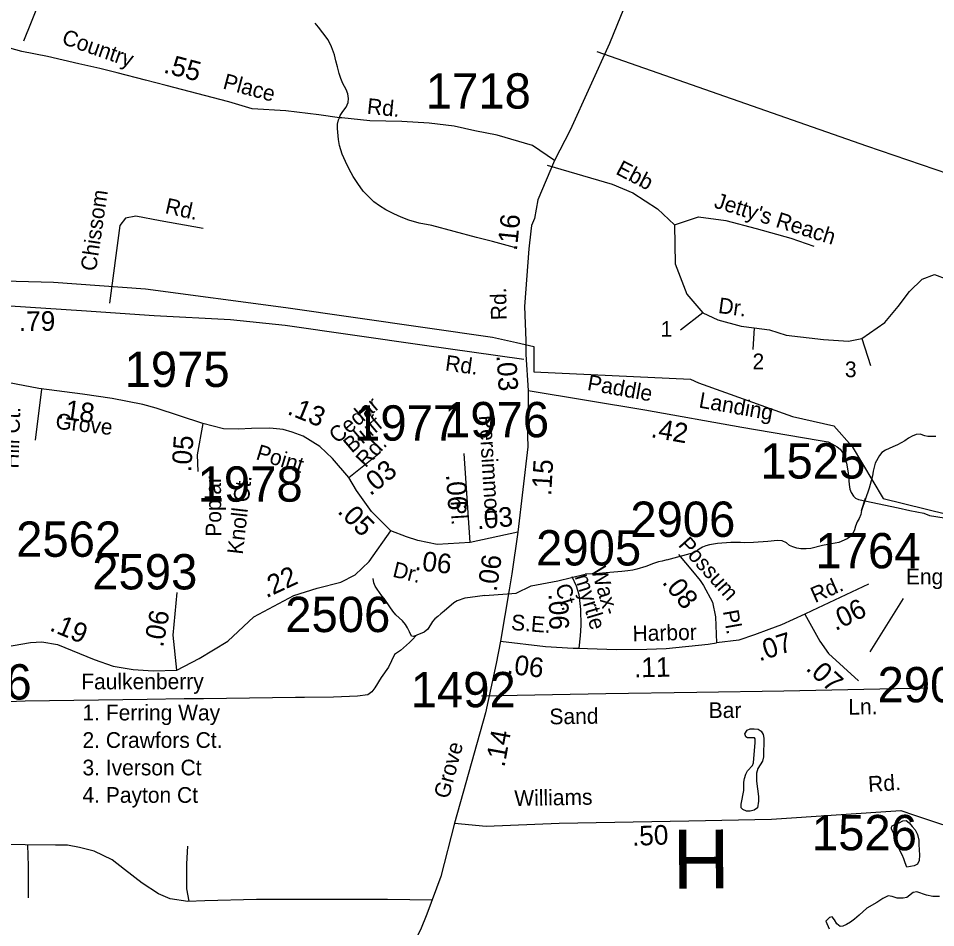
# Model space of a CAD drawing. Extents: x 1945482 to 2853149, y 66427 to 1015778.
# Drawn here: x 2335176 to 2339010, y 129311 to 133113 of the extents above; entities that cross this region are included whole.
import ezdxf

# ---------------------------------------------------------------- set-up
doc = ezdxf.new("R2010")
doc.units = 0
for name, color, linetype in [('Old_Level_10', 7, 'Continuous'), ('Old_Level_11', 7, 'Continuous'), ('Old_Level_17', 7, 'Continuous'), ('Old_Level_22', 7, 'Continuous'), ('Old_Level_32', 7, 'Continuous'), ('Old_Level_35', 7, 'Continuous'), ('Old_Level_50', 7, 'Continuous'), ('Old_Level_59', 7, 'Continuous'), ('Old_Level_60', 7, 'Continuous'), ('Old_Level_8', 7, 'Continuous')]:
    doc.layers.add(name, color=color, linetype=linetype)

msp = doc.modelspace()

# ---------------------------------------------------------------- linework, layer by layer
at = {"layer": 'Old_Level_11'}
msp.add_lwpolyline([(2338874.8, 130686.6), (2338735.5, 130464.3)], dxfattribs=at)
at = {"layer": 'Old_Level_32'}
msp.add_line((2337296.9, 131707.1), (2337306.5, 131557.2), dxfattribs=at)
for points in [[(2338269.9, 134469.8), (2338210.3, 134298.6), (2338141.2, 134156.7), (2338029, 133917.9), (2337971.8, 133774.7), (2337926.8, 133681.5), (2337881.7, 133575.2), (2337736.8, 133227.3), (2337646.7, 133008.3), (2337482.6, 132645.4), (2337417.3, 132518.6)], [(2337417.3, 132518.6), (2337325.2, 132580.9), (2337177.2, 132623.9), (2337084.2, 132643), (2336998.3, 132662.1), (2336893.3, 132674.1), (2336778.8, 132681.2), (2336644.7, 132683.7), (2336527.9, 132696.3), (2336518, 132697.5), (2336431.9, 132708.8), (2336294.3, 132725.5), (2336153.4, 132735.1), (2336056.6, 132763.2), (2335794.6, 132831.9), (2335707.2, 132853.7), (2335588.6, 132885), (2335516.9, 132903.7), (2335429.5, 132922.4), (2335298.5, 132953.6), (2335190.1, 132974.4), (2335073.8, 133006.7)], [(2337417.3, 132518.6), (2337347.8, 132353.3), (2337333.5, 132275.3), (2337320.8, 132246.7), (2337317.6, 132222.8), (2337310.1, 132148.8), (2337292.2, 131907.7), (2337296.9, 131766), (2337296.9, 131707.1)], [(2337288.4, 131685.7), (2336864, 131746.5), (2336290.8, 131828.4), (2336063.3, 131852.7), (2335744.1, 131869.4), (2335440, 131890.5), (2335141.6, 131909.2), (2335069.6, 131912.3), (2335007.5, 131913.8), (2334951.4, 131913.2), (2334907.5, 131912.8), (2334869.4, 131912.3), (2334835.4, 131909.9), (2334799.3, 131907.9), (2334666, 131893.1), (2334495.9, 131870.6), (2334240.3, 131832.4), (2333933.4, 131803.5), (2333526.6, 131748.4), (2333222.2, 131711.6), (2333101.9, 131703.9)], [(2335947.6, 131419), (2335752.8, 131483.3), (2335697.1, 131498.3), (2335567.8, 131523.9), (2335443.7, 131541.4), (2335261.5, 131564.6), (2335070.7, 131601.4)], [(2337306.5, 131557.2), (2337306.5, 131458.8), (2337303.3, 131414.3), (2337305.1, 131321.8), (2337263.4, 130963.7)], [(2337306.5, 131557.2), (2337795.2, 131475.6), (2338199.7, 131403.6), (2338518.6, 131348.9), (2338560.6, 131341.4), (2338579.7, 131332.3), (2338598.1, 131321.8), (2338611, 131311.8), (2338621.1, 131297.1), (2338629.3, 131280.1), (2338637.6, 131253.5), (2338644.5, 131212.4), (2338648.3, 131164.3), (2338651.4, 131144.1), (2338656.6, 131129.5), (2338667, 131114.5), (2338675.2, 131106.6), (2338687.3, 131100.5), (2338853.2, 131066.2), (2338902.9, 131054.8), (2338960.3, 131043.3), (2338985.1, 131033.7), (2339334.8, 130978.3)], [(2335947.6, 131419), (2335924, 131287.3), (2335926.3, 131218.6)], [(2336557, 131192.6), (2336489.5, 131271.7), (2336436.3, 131322.9), (2336366.7, 131365.8), (2336320.7, 131382.9), (2336283.2, 131393.6), (2336228, 131399.8), (2336150.7, 131397.6), (2336095.9, 131394.7), (2336033.2, 131396.5), (2335947.6, 131419)], [(2336557, 131192.6), (2336689.9, 131298.3)], [(2337065.3, 130920.5), (2337039.6, 131293.2)], [(2336733.6, 130969.8), (2336652.3, 131051.2), (2336590.2, 131137.9), (2336557, 131192.6)], [(2335838.6, 130387.5), (2335932.2, 130435.5), (2336051.4, 130509.1), (2336160.8, 130610.6), (2336327.8, 130700.1), (2336425.2, 130729.9), (2336524.6, 130755.8), (2336584.3, 130785.6), (2336642.6, 130842.3), (2336733.6, 130969.8)], [(2337065.3, 130920.5), (2336926.1, 130912.9), (2336846, 130930.1), (2336798.9, 130945.1), (2336733.6, 130969.8)], [(2337263.4, 130963.7), (2337065.3, 130920.5)], [(2337263.4, 130963.7), (2337239.5, 130790.6), (2337227.3, 130723.5), (2337191.7, 130508.3)], [(2337935.3, 130870.4), (2337994.5, 130801.2), (2338026.1, 130762), (2338040.3, 130741.2), (2338077.8, 130671.4), (2338090.3, 130609.7), (2338094.5, 130501.3)], [(2337489.6, 130778.5), (2337507.8, 130739.9), (2337518.8, 130703.4), (2337525.5, 130640.8), (2337527.2, 130574), (2337524.6, 130531.5), (2337518.3, 130479.1)], [(2338729.4, 130746.2), (2338492.3, 130634.9), (2338464, 130621.8)], [(2335838.6, 130387.5), (2335822.8, 130533), (2335840.3, 130711.6)], [(2338464, 130621.8), (2338365.4, 130577.5), (2338313, 130557.9), (2338253.6, 130534.4), (2338187.9, 130513.1), (2338094.5, 130501.3)], [(2338464, 130621.8), (2338525.8, 130508.6), (2338562.4, 130457.4), (2338688.4, 130342.2)], [(2338464, 130621.8), (2338525.8, 130508.6), (2338562.4, 130457.4), (2338688.4, 130342.2)], [(2334813.2, 130409.2), (2334949.8, 130429.7), (2335089.2, 130479.3), (2335226.4, 130503.2), (2335274.1, 130505.2), (2335339.7, 130495.2), (2335492.8, 130431.6), (2335572.3, 130403.7), (2335655.8, 130389.8), (2335739.3, 130383.8), (2335838.6, 130387.5)], [(2337191.7, 130508.3), (2337173.5, 130414.5), (2337129.2, 130208.7), (2336999.8, 129747.6)], [(2337191.7, 130508.3), (2337379.7, 130485.9), (2337495.3, 130479.6), (2337518.3, 130479.1)], [(2337518.3, 130479.1), (2337555.1, 130478.3), (2337675.8, 130473.2), (2337802.9, 130475.7), (2337884.5, 130478.5), (2338059.9, 130496.4), (2338094.5, 130501.3)], [(2336999.8, 129747.6), (2337131.7, 129735.1), (2337436.8, 129748), (2337978.5, 129757.9), (2338324.1, 129763.6), (2338864.3, 129799.9), (2338921.3, 129780.9), (2339039.3, 129741.9), (2339267.2, 129757.4)], [(2336999.8, 129747.6), (2336941.9, 129524.2), (2336883.7, 129367.1), (2336856.6, 129301.2), (2336804.6, 129200.6), (2336456.6, 128397.8), (2336312.3, 128078.6), (2336166, 127764.9), (2335959.9, 127274.1), (2335938.2, 127216)]]:
    msp.add_lwpolyline(points, dxfattribs=at)
at = {"layer": 'Old_Level_35'}
for points in [[(2335363.2, 133430.3), (2335197.3, 133017.7)], [(2336518, 132697.5), (2336521.7, 132706.3), (2336532.1, 132723.1), (2336546.8, 132742), (2336551.1, 132750.7), (2336554.3, 132761), (2336555.6, 132777.2), (2336553.5, 132797.1), (2336546.9, 132815.2), (2336532.7, 132840.9), (2336524.7, 132861), (2336517.3, 132882.3), (2336510, 132910.6), (2336503.8, 132934.6), (2336497.8, 132960.7), (2336485.7, 132994), (2336471.1, 133022.3), (2336448.6, 133052.3), (2336430.6, 133076.2), (2336416.2, 133092)], [(2337593.5, 132974.1), (2338721.8, 132579.2), (2339292, 132385.1)], [(2337250.1, 132154.1), (2337157.9, 132179.3), (2337091.5, 132196.7), (2336905.1, 132246.8), (2336850.9, 132256.2), (2336808.7, 132269.6), (2336776.7, 132281.4), (2336745.9, 132296), (2336712.5, 132312.7), (2336686.2, 132328.4), (2336661.9, 132346.2), (2336638.4, 132368.9), (2336617.5, 132389.7), (2336595.3, 132421.6), (2336576.3, 132452.1), (2336559.4, 132482.6), (2336543.7, 132514.1), (2336530, 132545.1), (2336518.7, 132581.1), (2336514.1, 132606.5), (2336510.9, 132636.6), (2336510, 132652), (2336510.6, 132670.7), (2336514.5, 132688.9), (2336518, 132697.5)], [(2337385.9, 132499.6), (2337658.7, 132419.8), (2337744, 132382.7), (2337847.9, 132315.9), (2337918.4, 132249.1), (2337922.1, 132085.7), (2337970.4, 131959.5), (2338037.2, 131881.5), (2338100.2, 131851.8), (2338196.7, 131825.8), (2338252.3, 131818.4), (2338315.4, 131810.9), (2338385.9, 131788.7), (2338541.7, 131770.1), (2338645.6, 131762.7), (2338701.3, 131773.8), (2338797.8, 131840.6), (2338853.4, 131907.5), (2338901.6, 131970.6), (2338953.6, 132022.6), (2339005.5, 132041.1), (2339057.5, 132022.6)], [(2335948, 132234.3), (2335768.4, 132265.6), (2335666.9, 132285.1), (2335623.9, 132277.3), (2335600.5, 132246), (2335557.6, 131921.8)], [(2337918.4, 132249.1), (2338018.6, 132282.5), (2338133.6, 132267.6), (2338259.8, 132234.2), (2338404.5, 132193.4), (2338500.9, 132159.9)], [(2338037.2, 131881.5), (2337944, 131809)], [(2338252.3, 131818.4), (2338246.8, 131728.7)], [(2338701.3, 131773.8), (2338738.6, 131661.3)], [(2335247.4, 131349.3), (2335274.8, 131562.9)], [(2337111.5, 130280.1), (2337631.3, 130289.5), (2338011.5, 130295.3), (2338375.2, 130301.2), (2338977.3, 130313.5)], [(2336905.4, 129425.7), (2336719.2, 129428.6), (2336172.2, 129428.6), (2335955.7, 129422.9), (2335884.5, 129420.6), (2335811.1, 129431.1), (2335762, 129451.4), (2335693.6, 129497.1), (2335619.5, 129554.1), (2335568.2, 129594), (2335492.9, 129630.5), (2335431.5, 129645.3), (2335381, 129655), (2335332.1, 129655), (2335076.8, 129658.5), (2334804.7, 129656.7), (2334548.3, 129645.3), (2334377.3, 129639.6), (2334143.7, 129633.9)], [(2335214.7, 129656.6), (2335216.7, 129567.5), (2335216.7, 129434.6)], [(2335889.7, 129420.8), (2335881, 129473.1), (2335881, 129578), (2335884.5, 129651.5)]]:
    msp.add_lwpolyline(points, dxfattribs=at)
at = {"layer": 'Old_Level_50'}
for points in [[(2333062.4, 137083), (2332916.3, 135282.8), (2332897.1, 135023.3), (2332954.7, 134437), (2333180.5, 131837.1), (2334688.9, 132000.4), (2334958, 132019.7), (2335323.1, 132010.1), (2335707.4, 131981.2), (2336293.5, 131904.3), (2337158.2, 131779.4), (2337257.8, 131757.2)], [(2337257.8, 131757.2), (2337331.1, 131740.9), (2337331.1, 131635.2), (2337985.3, 131604.6), (2338019.2, 131588.2), (2338412, 131447.8), (2338584.9, 131409.3), (2338661.8, 131322.8), (2338791.4, 131104.7), (2339498.8, 130930.2), (2339790.3, 130853)]]:
    msp.add_lwpolyline(points, dxfattribs=at)
at = {"layer": 'Old_Level_59'}
msp.add_line((2337887.2, 130848.7), (2337999, 130879.6), dxfattribs=at)
for points in [[(2339011.5, 131363.8), (2338977.2, 131363.8), (2338964.5, 131366.6), (2338946.2, 131374.4), (2338928.5, 131372.9), (2338912, 131365.6), (2338896.5, 131357.1), (2338881, 131346), (2338866.5, 131337.3), (2338850.2, 131328.9), (2338831.7, 131321.5), (2338801, 131306.8), (2338786, 131296.8), (2338776.2, 131284.3), (2338757, 131253), (2338749, 131219.3), (2338745.7, 131200.5), (2338740.7, 131179.1), (2338736, 131163.4), (2338732.7, 131147.8), (2338700, 131054.5), (2338716.5, 131106.3)], [(2338700, 131054.5), (2338697, 131038.6), (2338690.7, 131021), (2338682, 131007.2), (2338675.7, 130989.2), (2338671.7, 130974.5), (2338664.5, 130958.2), (2338654, 130946.7), (2338641, 130936.2), (2338605.2, 130921.8), (2338575.2, 130915.5), (2338538, 130908.9), (2338488, 130896), (2338468.7, 130894.6), (2338446.7, 130894.5), (2338430.5, 130897), (2338413.5, 130902.6), (2338399.2, 130908.7), (2338387.2, 130919.2), (2338369.2, 130927.8), (2338348.7, 130929.1), (2338309.2, 130924.7), (2338248.7, 130920.6), (2338212.2, 130920.4), (2338194.5, 130921.8), (2338154, 130921.8), (2338098.7, 130916.9), (2338081.2, 130914.7), (2338065, 130911.3), (2338050, 130907.2), (2338035.5, 130901), (2338021.7, 130893.3), (2338009.2, 130884.1), (2337999, 130879.6)], [(2337887.2, 130848.7), (2337867.5, 130843.2), (2337851.2, 130839.9), (2337830.5, 130833.8), (2337798.7, 130821), (2337760.7, 130809.7), (2337744, 130805.6), (2337723.2, 130802.4), (2337698.5, 130799.7), (2337648.5, 130795.2), (2337602, 130791.6), (2337545.5, 130789.1)], [(2337126.5, 130699.6), (2337257, 130709.9), (2337319.4, 130739.9), (2337430.5, 130761.4), (2337545.5, 130789.1)], [(2336838.4, 130532.7), (2336826.7, 130528.6), (2336819, 130530), (2336811.7, 130547.4), (2336803, 130564.4), (2336794, 130578.4), (2336782.2, 130593.8), (2336754.5, 130618.8), (2336741.7, 130634), (2336728.2, 130651.6), (2336705.5, 130686.4), (2336695.7, 130698.6), (2336676.2, 130725.8), (2336667.5, 130738.8), (2336661.5, 130753), (2336658.7, 130770.1)], [(2337126.5, 130699.6), (2337064.2, 130691.6), (2337042.2, 130687.8), (2337011, 130677.4), (2336996, 130668.4), (2336956, 130633.6), (2336942, 130623), (2336930.2, 130611.7), (2336917, 130602.2), (2336907, 130590.1), (2336887.2, 130559.2), (2336872, 130546.8), (2336841.7, 130533.9), (2336838.4, 130532.7)], [(2336838.4, 130532.7), (2336824.2, 130516.1), (2336810.7, 130502.7), (2336773.5, 130470.1), (2336749, 130452.1), (2336723, 130399.9), (2336693, 130356), (2336666, 130313), (2336654, 130296.2), (2336636.5, 130284.7), (2336593.5, 130278), (2336494, 130274.8), (2336372.2, 130273), (2336334.7, 130273.5), (2335950.5, 130268.1), (2335869.7, 130267.9), (2335714, 130264.8), (2335204, 130257.6), (2335093, 130253.2)]]:
    msp.add_lwpolyline(points, dxfattribs=at)
at = {"layer": 'Old_Level_60'}
for points in [[(2338219.7, 129797.3), (2338204.5, 129804.6), (2338197.5, 129811.1), (2338197.7, 129826.9), (2338208, 129884.6), (2338209.2, 129902), (2338209.2, 129918.6), (2338210.7, 129934.5), (2338217, 129951.8), (2338224.2, 129965.7), (2338245.2, 129988.1), (2338249.5, 130000), (2338255.7, 130084.5), (2338255.7, 130100.3), (2338252.5, 130104.8), (2338224.5, 130103.8), (2338216.7, 130108.8), (2338213, 130121.3), (2338222.5, 130136.4), (2338234.7, 130141.4), (2338252, 130142.1), (2338268, 130141.1), (2338281.5, 130132.1), (2338290, 130118.9), (2338291.5, 130102.9), (2338290.2, 130025.3), (2338286.5, 130006.5), (2338267.7, 129976.3), (2338262, 129956.9), (2338261.7, 129923.6), (2338270, 129858.4), (2338270, 129839.4), (2338265, 129811.7), (2338252, 129802), (2338235.7, 129797.4), (2338219.7, 129797.3)], [(2338890, 129563.6), (2338882.7, 129581.7), (2338877.5, 129598.7), (2338870.7, 129615.4), (2338861, 129632.7), (2338851.7, 129655.1), (2338843, 129680.5), (2338837, 129701.3), (2338825.7, 129722.7), (2338825.5, 129730.2), (2338828.7, 129736), (2338842.5, 129743.5), (2338858, 129749.3), (2338873.7, 129757.2), (2338887.7, 129758.1), (2338899.5, 129749.2), (2338912.7, 129734.2), (2338924.5, 129719), (2338935, 129699.5), (2338940.5, 129676.3), (2338940.5, 129658.1), (2338942.7, 129613.1), (2338941.2, 129591.2), (2338934, 129576.2), (2338920, 129568.8), (2338890, 129563.6)], [(2338972, 129446), (2338931.2, 129460.2), (2338916.2, 129457.4), (2338890.5, 129436.1), (2338874, 129433.8), (2338849.5, 129434.3), (2338829.2, 129440.8), (2338811.5, 129443.2), (2338789.7, 129433.2), (2338764, 129415.8), (2338722.7, 129392), (2338691, 129362.3), (2338671.7, 129345.7), (2338654.2, 129333.1), (2338637, 129323.8), (2338622, 129316.8), (2338610.7, 129316.1), (2338597.5, 129327.2), (2338588, 129343.3), (2338577.7, 129355.7), (2338566.2, 129352.4), (2338550.7, 129338.3), (2338564.7, 129305.8)], [(2339026.7, 129441.4), (2338998.2, 129440.8), (2338972, 129446)]]:
    msp.add_lwpolyline(points, dxfattribs=at)

# ---------------------------------------------------------------- texts
at = {"layer": 'Old_Level_10'}
for s, height, rotation, p in [('Ebb ', 65.62, 332.2986, (2337669.2, 132464.3)), ('Chissom', 65.62, 81.6008, (2335500.7, 132053.1)), ('Rd.', 65.62, 347.3529, (2335785.9, 132298.9)), ("Jetty's Reach", 65.617, 342.4859, (2338080, 132323)), ('Dr.', 65.62, 352.2143, (2338098.9, 131881.3)), ('Cedar ', 65.62, 40.3237, (2336509, 131332)), ('Hill Ct.', 65.62, 88.1728, (2335176.5, 131229.5)), ('Grove ', 65.62, 353.4399, (2335329.1, 131397.2)), ('Bluff', 65.62, 40.3237, (2336569.6, 131292.3)), ('Persimmon ', 65.62, 273.4829, (2337101.4, 131451.8)), ('Point', 65.62, 342.9771, (2336165.5, 131270.2)), ('Rd.', 65.62, 46.749, (2336627.6, 131230.7)), ('Poplar', 65.62, 90.5286, (2336025.2, 130945.5)), ('Knoll Ct.', 65.62, 83.4612, (2336114.1, 130868.9)), ('Pl.', 65.62, 273.4829, (2336982, 131094.5)), ('Dr.', 65.62, 346.254, (2336737, 130778.7)), ('Faulkenberry', 65.617, 0.113, (2335439.1, 130306.9)), ('Bar', 65.62, 0.095, (2338061.8, 130187.2)), ('Ln.', 65.62, 1.0742, (2338645.8, 130201)), ('Sand', 65.62, 0.8911, (2337396.5, 130160.4))]:
    msp.add_text(s, height=height, rotation=rotation, dxfattribs=at).set_placement(p)
for s, height, p in [('1', 65.6, (2337860.5, 131781.1)), ('2', 65.6, (2338244.9, 131645.5)), ('3', 65.6, (2338631, 131612.4)), ('English Landing', 65.617, (2338885.9, 130745.8))]:
    msp.add_text(s, height=height, dxfattribs=at).set_placement(p)
at = {"layer": 'Old_Level_11'}
for s, rotation, p in [('Country', 340.8069, (2335353.5, 133007.7)), ('Place', 345.0573, (2336027.4, 132820.1)), ('Rd.', 354.1765, (2336631.2, 132714.1)), ('Rd.', 90.89, (2337217.1, 131851.1)), ('Rd.', 352.2075, (2336957.6, 131640.7)), ('Paddle', 349.658, (2337551.1, 131559.6)), ('Landing', 349.912, (2338017.5, 131486)), ('Possum', 311.9957, (2337931.1, 130908.5)), ('Wax-', 286.7968, (2337568.1, 130809.3)), ('myrtle', 286.7968, (2337501.3, 130779.1)), ('Ct.', 286.7968, (2337419.6, 130738.1)), ('Rd.', 23.9071, (2338506, 130667.6)), ('Pl.', 280.0806, (2338120.5, 130634)), ('S.E.', 355.4586, (2337234, 130555.6)), (' Harbor', 1.3534, (2337719.8, 130507.5)), ('Grove', 75.1488, (2336974.9, 129846.2)), ('Rd.', 3.7426, (2338730.1, 129877.8)), ('Williams', 0.9983, (2337249.8, 129819.2))]:
    msp.add_text(s, height=65.62, rotation=rotation, dxfattribs=at).set_placement(p)
for s, p in [('1. Ferring Way', (2335444.3, 130177.1)), ('2. Crawfors Ct.', (2335444.3, 130062.3)), ('3. Iverson Ct', (2335444.3, 129947.4)), ('4. Payton Ct', (2335444.3, 129832.6))]:
    msp.add_text(s, height=65.617, dxfattribs=at).set_placement(p)
at = {"layer": 'Old_Level_17'}
for s, rotation, p in [('.55', 345.3153, (2335779.3, 132886.8)), ('.16', 84.1993, (2337259.6, 132138.6)), ('.79', 0.5863, (2335178.5, 131805)), ('.03', 273.6433, (2337174.7, 131703.7)), ('.18', 351.9989, (2335337.2, 131441.1)), ('.13', 337.8436, (2336296.2, 131459.5)), ('.42', 349.912, (2337816.9, 131362.1)), ('.05', 85.9124, (2335897.8, 131214.3)), ('.03', 39.2755, (2336647.3, 131113.7)), ('.15', 86.6112, (2337403, 131114.5)), ('.06', 273.9471, (2336963.3, 131205.1)), ('.05', 315.0144, (2336506.7, 131048)), ('.03', 5.2448, (2337095, 130976.1)), ('.06', 353.6626, (2336831, 130806.5)), ('.06', 81.6839, (2337175.2, 130713.3)), ('.22', 25.0083, (2336212.7, 130687.6)), ('.08', 308.934, (2337864.1, 130753.7)), ('.06', 271.3896, (2337392.7, 130707.1)), ('.06', 26.2431, (2338591.5, 130549.9)), ('.06', 79.5882, (2335780.6, 130480.2)), ('.19', 337.4209, (2335302.8, 130554.8)), ('.07', 17.9781, (2338273.3, 130423.4)), ('.06', 353.1981, (2337215.5, 130373.3)), ('.11', 1.1467, (2337750.2, 130357.1)), ('.07', 317.3668, (2338463.8, 130390.5)), ('.14', 79.6228, (2337207.8, 129979)), ('.50', 2.4674, (2337742.5, 129652.3))]:
    msp.add_text(s, height=82.02, rotation=rotation, dxfattribs=at).set_placement(p)
at = {"layer": 'Old_Level_22'}
msp.add_text('H', height=246.1, rotation=180.455, dxfattribs=at).set_placement((2338147.9, 129721.3))
at = {"layer": 'Old_Level_8'}
for s, p in [('1718', (2336879, 132735.4)), ('1975', (2335620.2, 131571.4)), ('1977', (2336579.5, 131347.1)), ('1976', (2336955.5, 131361.1)), ('1525', (2338277.1, 131188.5)), ('1978', (2335925.3, 131091.8)), ('2906', (2337733.9, 130944.6)), ('2562', (2335167, 130861.3)), ('2905', (2337340.3, 130825)), ('1764', (2338508, 130813.1)), ('2593', (2335485.1, 130724.9)), ('2506', (2336291.7, 130546.5)), ('2506', (2334792.7, 130264.5)), ('2907', (2338767.5, 130252.9)), ('1492', (2336816, 130232.1)), ('1526', (2338493, 129634.3))]:
    msp.add_text(s, height=147.64, dxfattribs=at).set_placement(p)

doc.saveas('drawing.dxf')
